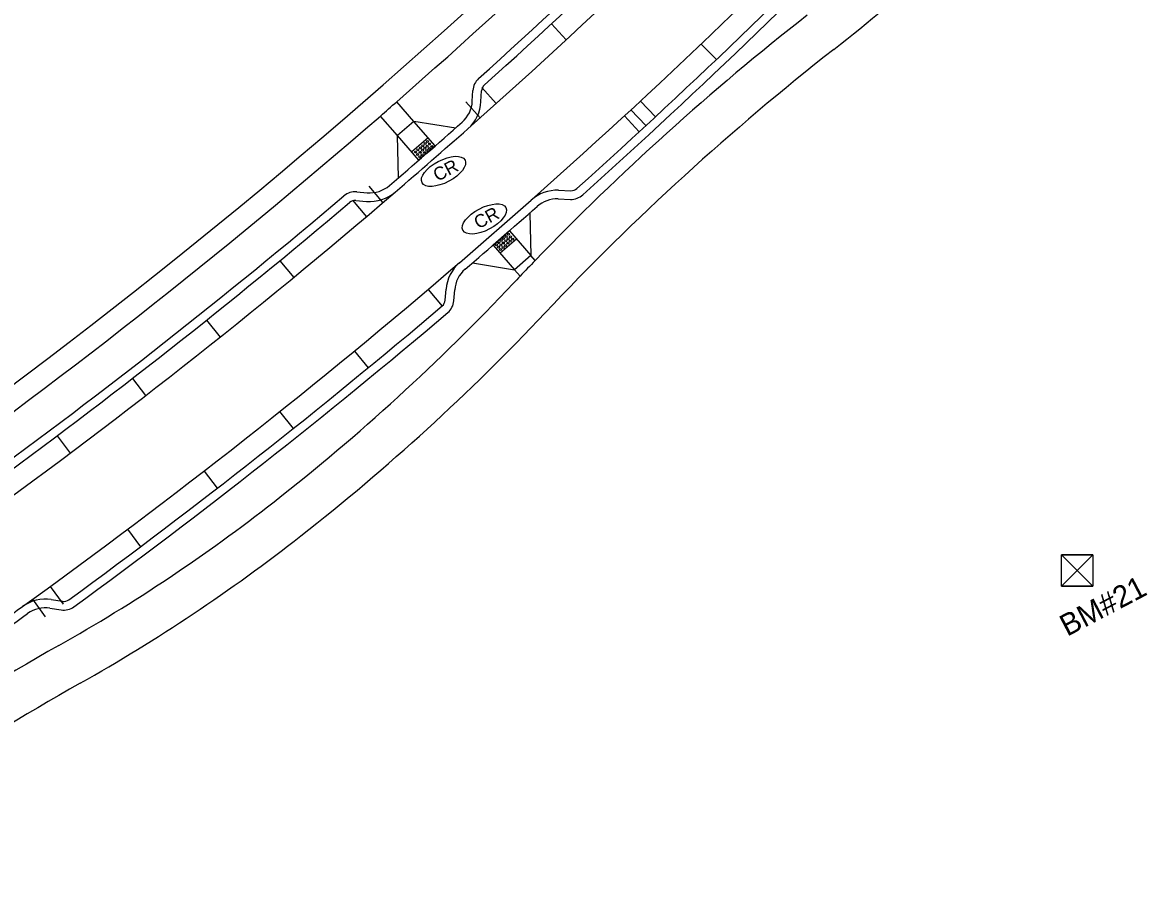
# Model space of a CAD drawing. Extents: x 1486489 to 1490134, y 497089 to 500876.
# Drawn here: x 1488292.7 to 1488552.5, y 498565.7 to 498768.1 of the extents above; entities that cross this region are included whole.
import ezdxf

# ---------------------------------------------------------------- set-up
doc = ezdxf.new("R2010")
doc.units = 0
for name, color, linetype in [('Default', 7, 'Continuous'), ('Prop Horizontal Alignment Station Label', 7, 'Continuous'), ('Scratch_Level_0', 7, 'Continuous'), ('Scratch_Level_5', 7, 'Continuous'), ('Sheet Block Title CELL', 7, 'Continuous'), ('Sheet Border Standard 30in CELL', 7, 'Continuous'), ('Sheet Sticker Exception Certification CELL', 7, 'Continuous')]:
    doc.layers.add(name, color=color, linetype=linetype)

msp = doc.modelspace()

# ---------------------------------------------------------------- linework, layer by layer
at = {"layer": 'Default'}
msp.add_line((1488535.85, 498641.76), (1488535.85, 498641.76), dxfattribs=at)
msp.add_lwpolyline([(1488532.25, 498645.35), (1488539.44, 498645.35), (1488539.44, 498638.16), (1488532.25, 498638.16)], close=True, dxfattribs=at)
for points in [[(1488539.44, 498645.35), (1488532.25, 498638.16), (1488535.85, 498641.76), (1488539.44, 498638.16), (1488532.25, 498645.35)], [(1488535.85, 498641.76), (1488539.44, 498645.35), (1488532.25, 498645.35), (1488535.85, 498641.76)], [(1488535.85, 498641.76), (1488532.25, 498638.16), (1488539.44, 498638.16), (1488535.85, 498641.76)]]:
    msp.add_lwpolyline(points, dxfattribs=at)
at = {"layer": 'Prop Horizontal Alignment Station Label'}
for centre, radius, start, end in [((1487424.96, 499839.79), 1443.5, 305.25533, 321.11565), ((1487424.96, 499839.79), 1448.5, 311.19416, 321.11565), ((1488230.2, 499080.88), 405, 308.0345, 316.6966), ((1488846.34, 498293.24), 605, 128.03451, 136.03603), ((1488846.34, 498293.24), 595, 128.03451, 136.72216), ((1487424.96, 499839.79), 1448.5, 310.99638, 311.19416), ((1487424.96, 499839.79), 1448.5, 305.25533, 310.99638), ((1488846.34, 498293.24), 605, 136.03603, 136.51149), ((1488846.34, 498293.24), 605, 136.51149, 136.72216), ((1488045.49, 499047.33), 495, 308.0626, 316.7222), ((1488045.49, 499047.33), 505, 308.0626, 316.7222), ((1488107.15, 498968.6), 395, 299.4005, 308.0626), ((1488107.15, 498968.6), 405, 299.4005, 308.0626), ((1488598.06, 498097.39), 605, 119.40053, 128.08818), ((1488598.06, 498097.39), 595, 119.40053, 128.08818)]:
    msp.add_arc(centre, radius, start, end, dxfattribs=at)
at = {"layer": 'Scratch_Level_0'}
for p, q in [((1488382.91, 498745.29), (1488378.97, 498749.82)), ((1488379.14, 498742.01), (1488375.2, 498746.53)), ((1488382.91, 498745.29), (1488379.14, 498742.01)), ((1488387.84, 498739.64), (1488382.91, 498745.29)), ((1488392.55, 498743.75), (1488382.91, 498745.29)), ((1488384.07, 498736.35), (1488379.14, 498742.01)), ((1488379.36, 498732.25), (1488379.14, 498742.01)), ((1488386.2, 498741.53), (1488382.43, 498738.24)), ((1488387.84, 498739.64), (1488384.07, 498736.35)), ((1488409.64, 498724.15), (1488409.86, 498714.39)), ((1488404.93, 498720.05), (1488401.16, 498716.76)), ((1488404.93, 498720.05), (1488409.86, 498714.39)), ((1488401.16, 498716.76), (1488406.08, 498711.11)), ((1488406.57, 498718.16), (1488402.8, 498714.88)), ((1488409.86, 498714.39), (1488406.08, 498711.11)), ((1488410.87, 498713.23), (1488409.86, 498714.4)), ((1488396.45, 498712.65), (1488406.08, 498711.11)), ((1488407.4, 498709.61), (1488406.09, 498711.11))]:
    msp.add_line(p, q, dxfattribs=at)
for centre in [(1488384.41, 498739.2), (1488384.96, 498739.68), (1488385.44, 498739.13), (1488385.52, 498740.17), (1488386, 498739.61), (1488386.07, 498740.65), (1488386.48, 498739.06), (1488386.55, 498740.09), (1488387.04, 498739.54), (1488383.3, 498738.23), (1488383.3, 498738.23), (1488383.78, 498737.68), (1488383.78, 498737.68), (1488383.85, 498738.72), (1488384.26, 498737.12), (1488384.34, 498738.16), (1488384.82, 498737.61), (1488384.89, 498738.64), (1488385.37, 498738.09), (1488385.93, 498738.57), (1488403.61, 498718.3), (1488404.17, 498718.78), (1488404.72, 498719.27), (1488405.2, 498718.71), (1488401.95, 498716.85), (1488402.43, 498716.3), (1488402.43, 498716.3), (1488402.5, 498717.33), (1488402.91, 498715.74), (1488402.91, 498715.74), (1488402.98, 498716.78), (1488403.06, 498717.82), (1488403.47, 498716.22), (1488403.54, 498717.26), (1488404.02, 498716.71), (1488404.09, 498717.75), (1488404.58, 498717.19), (1488404.65, 498718.23), (1488405.13, 498717.67), (1488405.69, 498718.16)]:
    msp.add_circle(centre, 0.222, dxfattribs=at)
for centre in [(1488389.75, 498733.77), (1488399.17, 498722.8)]:
    msp.add_ellipse(centre, major_axis=(4.96, 2.62), ratio=0.462467, dxfattribs=at)
at = {"layer": 'Scratch_Level_5'}
for p, q in [((1488396.39, 498749.97), (1488396.51, 498752.41)), ((1488369.73, 498729.06), (1488372.16, 498728.85)), ((1488416.19, 498727.41), (1488419.01, 498727.32)), ((1488392.13, 498703.96), (1488392.32, 498706.43)), ((1488299.02, 498633.06), (1488301.58, 498632.67))]:
    msp.add_line(p, q, dxfattribs=at)
for centre, radius, start, end in [((1487424.96, 499839.79), 1457, 311.89155, 316.09919), ((1487424.96, 499839.79), 1493, 311.89155, 316.0979), ((1488400.51, 498752.2), 4, 131.8915, 177.0252), ((1488389.4, 498750.34), 7, 311.5168, 357.0252), ((1487424.96, 499839.79), 1462, 310.64727, 311.51677), ((1488369.39, 498725.07), 4, 85.1389, 130.2725), ((1488372.75, 498735.83), 7, 265.1389, 310.6473), ((1487424.96, 499839.79), 1457, 306.06486, 310.2725), ((1488415.95, 498720.42), 7, 87.994, 131.5186), ((1488419.15, 498731.31), 4, 267.994, 312.8618), ((1487424.96, 499839.79), 1488, 310.67191, 311.51863), ((1488399.3, 498705.9), 7, 130.6719, 175.6511), ((1488388.14, 498704.26), 4, 310.2409, 355.6511), ((1487424.96, 499839.79), 1493, 306.09563, 310.30513), ((1488297.95, 498626.15), 7, 81.2346, 125.7279), ((1488302.19, 498636.62), 4, 261.2346, 306.0956), ((1487424.96, 499839.79), 1488, 304.81445, 305.72786)]:
    msp.add_arc(centre, radius, start, end, dxfattribs=at)
at = {"layer": 'Sheet Block Title CELL'}
for p, q in [((1488414.65, 498767.78), (1488418.04, 498764.1)), ((1488449.14, 498763.1), (1488452.65, 498759.53)), ((1488432.97, 498747.94), (1488436.42, 498744.32)), ((1488352.03, 498713.18), (1488355.21, 498709.32)), ((1488335.12, 498699.48), (1488338.24, 498695.58)), ((1488369.19, 498692.34), (1488372.36, 498688.48)), ((1488318.02, 498686.04), (1488321.08, 498682.08)), ((1488351.97, 498678.38), (1488355.09, 498674.47)), ((1488300.71, 498672.84), (1488303.71, 498668.84)), ((1488334.54, 498664.68), (1488337.6, 498660.73)), ((1488316.92, 498651.25), (1488319.92, 498647.25))]:
    msp.add_line(p, q, dxfattribs=at)
for radius, start, end in [(1464, 311.51677, 316.47396), (1486, 311.51863, 316.46337), (1464, 305.69008, 310.64727), (1486, 305.72786, 310.67191)]:
    msp.add_arc((1487424.96, 499839.79), radius, start, end, dxfattribs=at)
at = {"layer": 'Sheet Border Standard 30in CELL'}
for p, q in [((1488398.55, 498753.14), (1488401.89, 498749.41)), ((1488394.86, 498749.84), (1488398.19, 498746.11)), ((1488435.19, 498749.99), (1488438.59, 498746.33)), ((1488435.19, 498749.99), (1488438.59, 498746.33)), ((1488431.49, 498746.57), (1488434.87, 498742.9)), ((1488372.5, 498730.34), (1488375.74, 498726.54)), ((1488368.73, 498727.14), (1488371.97, 498723.32)), ((1488386.2, 498706.55), (1488389.43, 498702.73)), ((1488299.09, 498638.08), (1488302.03, 498634.03)), ((1488295.01, 498635.12), (1488297.94, 498631.07))]:
    msp.add_line(p, q, dxfattribs=at)
at = {"layer": 'Sheet Sticker Exception Certification CELL'}
for p, q in [((1488398.38, 498749.87), (1488398.51, 498752.31)), ((1488416.26, 498729.41), (1488419.08, 498729.31)), ((1488369.56, 498727.07), (1488371.99, 498726.86)), ((1488393.43, 498712.72), (1488409.98, 498727.16)), ((1488390.13, 498704.11), (1488390.32, 498706.58)), ((1488299.32, 498635.04), (1488301.88, 498634.65))]:
    msp.add_line(p, q, dxfattribs=at)
for centre, radius, start, end in [((1487424.96, 499839.79), 1459, 311.89155, 316.09919), ((1487424.96, 499839.79), 1491, 311.89078, 316.0979), ((1488400.51, 498752.2), 2, 131.8915, 177.0252), ((1488389.4, 498750.34), 9, 311.5168, 357.0252), ((1487424.96, 499839.79), 1464, 310.64727, 311.51677), ((1488372.75, 498735.83), 9, 265.1389, 310.6473), ((1488415.95, 498720.42), 9, 87.994, 131.5186), ((1488419.15, 498731.31), 2, 267.994, 313.2638), ((1487424.96, 499839.79), 1459, 306.06486, 310.2725), ((1488369.39, 498725.07), 2, 85.1389, 130.2725), ((1488399.3, 498705.9), 9, 130.6719, 175.6511), ((1488388.14, 498704.26), 2, 310.3053, 355.6511), ((1487424.96, 499839.79), 1491, 306.09563, 310.3053), ((1487424.96, 499839.79), 1486, 304.81445, 305.72786), ((1488297.95, 498626.15), 9, 81.2346, 125.7279), ((1488302.19, 498636.62), 2, 261.2346, 306.0956)]:
    msp.add_arc(centre, radius, start, end, dxfattribs=at)

# ---------------------------------------------------------------- texts
at = {"layer": 'Default'}
msp.add_text('BM#21', height=5, rotation=27.6924, dxfattribs=at).set_placement((1488533.53, 498626.46))
at = {"layer": 'Scratch_Level_0'}
for p in [(1488388.36, 498731.36), (1488397.78, 498720.4)]:
    msp.add_text('CR', height=3, rotation=27.8351, dxfattribs=at).set_placement(p)

doc.saveas('drawing.dxf')
